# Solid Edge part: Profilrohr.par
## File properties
Username: bmolnar
Dokumentum tartalom típus: 0
Author: bmolnar
Last saved by: bmolnar
Revision: 81
Sűrűség: 0,000 kg/m^3
Pontosság: 0,990
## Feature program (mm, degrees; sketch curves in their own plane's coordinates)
base feature "unnamed BaseFeature 1"
thread "unnamed Thread 1"
thread "Menet_2"  ThreadDepth = 6 mm
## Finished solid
Body 1: solid body, 153 faces, 364 edges, 236 vertices.
  Faces by surface: plane 74, cylinder 65, cone 10, torus 4
  Edges by curve: line 220, circle 140, curve on surface 2, spline 2
Bounding box of the edges (mm; curved faces can reach further): 46.000 x 51.000 x 54.500, from (-23, -24, 0) to (23, 27, 54.5).
Cylindrical faces by radius (mm): R0.3 x24, R0.8 x2, R2.9 x8, R4.283 x4, R4.4 x16, R16 x1, R16.85 x2, R17.05 x2, R17.9 x2, R30 x4
Conical faces (half-angle, radius in mm at the cone's reference point): 21 deg R16.325 x2, 45 deg R4.783 x2, 45 deg R17.1 x2, 45 deg R17.15 x2, 45 deg R17.2 x2
Toroidal faces (ring radius, tube radius in mm): R17.7 r0.2 x4
Planar faces by outward normal: +x 6, +y 9, +z 8, -x 6, -y 5, -z 8, oblique 32
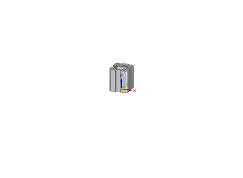
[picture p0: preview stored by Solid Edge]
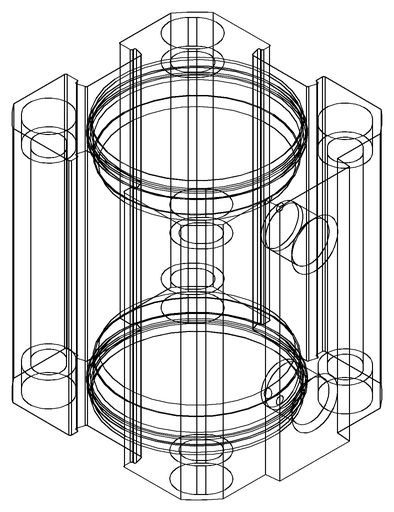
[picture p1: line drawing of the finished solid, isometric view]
